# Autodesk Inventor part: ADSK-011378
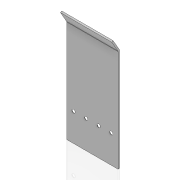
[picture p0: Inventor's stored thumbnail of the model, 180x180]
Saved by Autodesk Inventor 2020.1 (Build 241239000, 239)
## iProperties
Created: 1999-12
Part Number: ADSK-011378
Material: 1.0312 DC05
Description: FSHTPH,SS,CP,01,089,006,040,030,MNT,CLAMP/SLIDE
Document SubType Name: Tôlerie
Designer: glanglot
Density: 1 g/cm^3
Sheet Metal Rule: Stahlblech 1.0312 - DC05 -   3.0 mm
Appearance: Chrom - poliert
Mass: 69.1182 g
Surface Area: 485.321 cm^2
Volume: 69.1182 cm^3
Flat Pattern Width: 22.8654 cm
Flat Pattern Length: 10.2 cm
Flat Pattern Area: 233.227 cm^2
Sheet Metal Width: 228,654 mm
Sheet Metal Length: 102,000 mm
Sheet Metal Area: 23322,734 mm^2
Control State: 0
Checked Out: False
Master: False
Shininess: 57.0
Length Units: 11269
Angle Units: 11279
Time Units: 11290
Mass Units: 11283
Length Display Precision: 3
Angle Display Precision: 2
Compacted: True
CUTLENGTH: 4.00 X 9.03 (37 SI)
MATERIAL DESC: SHEET,S/S, 11 GA
MATERIAL_NUMBER: A084638
G_L: 102x228,7 mm
Thickness: 3,000 mm
Dimensions: 102x226,2x15,5 mm
Mass: 0,069 kg
Semi finished: Stahlblech 1.0312 - DC05 -   3.0 mm
Density: 8.03
Volumn: 73.2761274471973
Area: 486.69643206521
PropertySet Name: Model Information
Author: glanglot
Revision Number: -
Title: FSHTPH,SS,CP,01,089,006,040,030,MNT,CLAMP/SLIDE
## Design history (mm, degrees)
node "Solide1"
  node "Extrusion3" dims "d43" = 102, "d44" = 0
  node "Fillet3" dims "d45" = 3 (= X1)
  node "Fillet4" dims "d46" = 6 (= 2 x X1)
  node "Hole2" dims "d56" = 5.5, "d57" = 12.5, "d58" = 6.35, "d59" = 90 deg, "d60" = 19.05, "d61" = 118 deg, "d67" = 6
node "FlatPattern"
sketch "Sketch3"
  geometry: L1 (203.804, 0)-(0, 0); L2 (0, 0)-(0, 3); L3 (0, 3)-(203, 3); L4 (203, 3)-(224.651, 15.5); L5 (224.651, 15.5)-(226.151, 12.902); L6 (226.151, 12.902)-(203.804, 0); 1 further point
  constraints: 12 end point, 2 parallel, 2 perpendicular, 1 coincident, 1 horizontal
  dimensions: "d37" = 150 deg angle of L3 L4 (computed from X5); "d38" = 203 distance of L2.end L3.end; "d39" = 25 distance of L3.end L4.end; "d41" = 3 distance of L4.end L5.end (= X1); "d42" = 3 distance of L1.end L2.end (= X1)
workplane "Work Plane1"
sketch "Sketch5"
  geometry: L1 (102, 0)-(0, 0) reference; L2 (88.5, 55.5)-(13.5, 55.5); 5 further points
  constraints: 2 end point, 2 midpoint, 2 point on line, 1 coincident, 1 horizontal, 1 vertical alignment
  dimensions: "d49" = 25 distance of point (38.5, 55.5) point (13.5, 55.5); "d62" = 25 distance of point (63.5, 55.5) point (38.5, 55.5) (= d49); "d63" = 25 distance of L2.start point (63.5, 55.5) (= d49); "d66" = 55.5 distance from line of L1 L2.start
node "Corps solides"
node "Corps surfaciques"
feature "Extrusion_mise_à_plat2" dims "d0" = 3 (derived)
other parameters: "X1" = 3 [user parameter; used in 4 equation terms], "X2" = 203.2 [user parameter], "X3" = 101.6 [user parameter; used in 1 equation term], "X4" = 25.4 [user parameter], "X5" = 30 deg [user parameter; used in 1 equation term], "d47" = -50.8 (= -0.5 x X3), "Thickness" = 3 (derived), "BendRadius" = 3 (= Thickness), "BendReliefWidth" = 3 (= Thickness), "BendReliefDepth" = 1.5 (= 0.5 x Thickness), "CornerReliefSize" = 12 (= 4 x Thickness), "SeamGap" = 0.00508, "MinimumRemnant" = 6 (= 2 x Thickness), "TransitionRadius" = 3 (= BendRadius), "TailleRayonJacobi" = 3 (= BendRadius), "TailleJeu" = 3 (= Thickness)
